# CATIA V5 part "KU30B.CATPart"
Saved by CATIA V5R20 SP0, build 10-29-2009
Part number: KU30B
Definition: UNKNOWN
Nomenclature: KU30B
Source: Unknown
Bounding box of the stored display mesh (mm): x -27.5 to 27.5, y -27.5 to 27.5, z -23.7 to 13.8
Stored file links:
  C:\Users\Utente\Desktop\IO LAVORO\3D X SITO CF\X 3D SITO CF 27-09-2020\KU30B\KU30B.CATPart
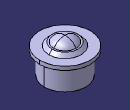
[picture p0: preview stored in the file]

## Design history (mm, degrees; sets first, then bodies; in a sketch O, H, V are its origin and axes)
Body1 "NONE" (main body)
  Solid1: solid without history
Body2 "NONE"
  Solid2: solid without history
